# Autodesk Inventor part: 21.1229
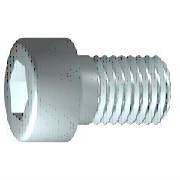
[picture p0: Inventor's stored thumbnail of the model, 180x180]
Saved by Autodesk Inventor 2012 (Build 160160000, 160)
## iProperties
IsCustomPart: 1
Created: 2006-02
Part Number: 21.1229
Material: Steel, Mild
Description: M4X12 SHCS
Document SubType Name: Modeling
Standard: DIN 7984
Designer: Andy Moles
Standards Organization: DIN
Language: en-US
Size Designation: M4 x 12
Categories: <MemberInstance><Categories><Category DisplayName="Fasteners" InternalName="e4da775c-781d-43d5-af7c-5136215cf5a6" Mnemonic="FSTN"><Category DisplayName="Bolts"
Density: 7.86 g/cm^3
Mass: 1.90624 g
Surface Area: 3.03485 cm^2
Volume: 0.242524 cm^3
Vendor: S
Title: M4x12 SHCS ZINC PLATED
Author: Andy Moles
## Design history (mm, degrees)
body "Solid1"
workplane "Work Plane1"
revolve "Body" stored, may be unused: angle "d10" = 90 deg
sketch "Sketch2"
  geometry: L1 (0, -4.2)-(0, 5.6) reference; L2 (-4.2, 0)-(5.6, 0) reference; L3 (1.443, 0)-(0.722, -1.25); L4 (0.722, -1.25)-(-0.722, -1.25); L5 (-0.722, -1.25)-(-1.443, 0); L6 (-1.443, 0)-(-0.722, 1.25); L7 (-0.722, 1.25)-(0.722, 1.25); L8 (0.722, 1.25)-(1.443, 0); 2 further points
  constraints: 12 end point, 1 coincident, 1 horizontal alignment, 1 point on line, 12 other
extrude "Slot" join sketch "Sketch2" stored distance "d11" = 10; taper "d12" = 0 deg
fillet "Fillet1" dims "d17" = 0.4 (= RR)
feature "Thread" dims "d13" = 12, "d14" = 0
chamfer "Chamfer1" distance "d15" = 0.42941 (= -0.5 x SPD + 0.5 x GD); stored, may be unused: second distance "d16" = 0.42941 (= GUL), angle "d27" = 45 deg
sketch "Sketch1"
  geometry: L1 (0.333, 0)-(12, 0); L2 (12, 0)-(12, 2); L3 (12, 2)-(2.1, 2); L4 (2.1, 2)-(1.67, 2); L5 (1.67, 2)-(0, 2); L6 (0, 2)-(0, 3.5); L7 (0, 3.5)-(-2.8, 3.5); L8 (-2.8, 3.5)-(-2.8, 1.443); L9 (-2.8, 1.443)-(-0.5, 1.443); L10 (-0.5, 1.443)-(0.333, 0); L11 (-4.28, 0)-(16.44, 0) reference; L12 (0, -0.35)-(0, 4.55) reference; L13 (2.1, 2)-(0, 2)
  constraints: 22 end point, 6 parallel, 2 collinear, 2 perpendicular, 1 horizontal, 1 point on line
  dimensions: "d1" = 9.9 distance from line of L3.end L2 (= GEL); "d2" = 0.42952 distance of L4.end L3.end (computed from GAL); "d3" = 2.8 distance between parallel lines of L8 L6 (= KOH); "d4" = 2.3 distance of L8.end L9.end (= INTI); "d5" = 60 deg angle of L10 L1; "d6" = 4 diameter of L3 L1 (= GD); "d7" = 4 diameter of L5 L1 (= BDM); "d8" = 2.88675 diameter of L9 L1 (= 1.1547 x SW); "d9" = 7 diameter of L7 L1 (= KOD); "d26" = 12 distance between parallel lines of L12 L2 (= NLG)
other parameters: "GD" = 4 (= NND) [user parameter; used in 2 equation terms], "NLG" = 12 [user parameter; used in 1 equation term], "GEL" = 9.9 [user parameter; used in 1 equation term], "KOD" = 7 [user parameter; used in 1 equation term], "KOH" = 2.8 [user parameter; used in 1 equation term], "INTI" = 2.3 [user parameter; used in 1 equation term], "GAL" = 0.42941 (= 0.61345 x PTC) [user parameter; used in 1 equation term], "GUL" = 0.42941 (= 0.61345 x PTC) [user parameter; used in 1 equation term], "BDM" = 4 (= NND) [user parameter; used in 1 equation term], "SW" = 2.5 [user parameter; used in 2 equation terms], "RR" = 0.4 [user parameter; used in 1 equation term], "SPD" = 3.14117 (= NND - 1.2269 x PTC) [user parameter; used in 1 equation term], "d19" = 0, "d28" = 0, "d29" = 0, "TOA" = 30 deg [user parameter], "GD1" = 3.14117 (= THREADDIA - 1.2269 x PTC) [user parameter], "THREADDIA" = 4 [user parameter; used in 1 equation term], "FAWI" = 45 deg [user parameter], "ANG" = 120 deg [user parameter], "TPU" = 14.28571 (computed from PTC) [user parameter], "PTC" = 0.7 [user parameter; used in 5 equation terms], "NND" = 4 [user parameter; used in 3 equation terms], "E0" = 2.8875 (= 1.155 x SW) [user parameter]
